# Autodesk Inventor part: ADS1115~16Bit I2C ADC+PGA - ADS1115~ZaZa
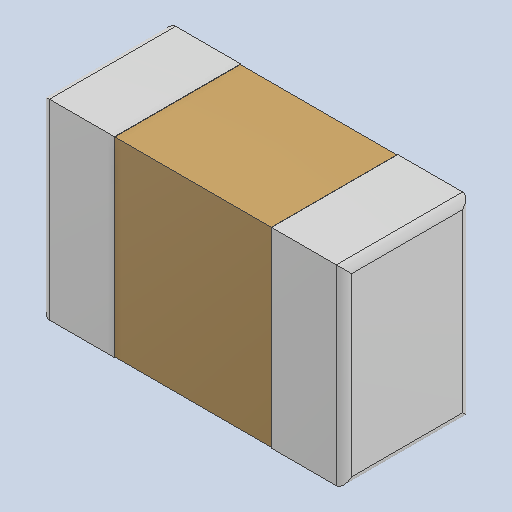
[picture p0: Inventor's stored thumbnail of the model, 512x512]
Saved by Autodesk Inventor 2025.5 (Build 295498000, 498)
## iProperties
Created: 2026-10
Part Number: ADS1115~16Bit I2C ADC+PGA - ADS1115~ZaZa
Material: Genérico
Description: 0805 Capacitor
Document SubType Name: Modeling
Designer: Luis M
Density: 1 g/cm^3
Appearance: Valor por defecto
Author: Luis M
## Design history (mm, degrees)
feature "Base1"
node "Sólido1"
